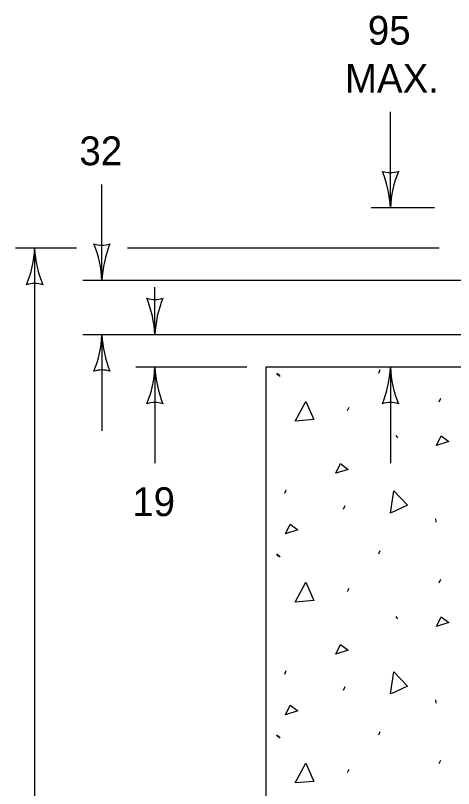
# Model space of a CAD drawing. Extents: x 49940 to 50043, y 49986 to 50011.
# Drawn here: x 50026.782 to 50027.696, y 49992.517 to 49994.127 of the extents above; entities that cross this region are included whole.
import ezdxf

# ---------------------------------------------------------------- set-up
doc = ezdxf.new("R2010")
doc.units = 0
for name, color, linetype in [('Level 1', 7, 'Continuous'), ('Level 2', 7, 'Continuous'), ('Level 3', 7, 'Continuous')]:
    doc.layers.add(name, color=color, linetype=linetype)

msp = doc.modelspace()

# ---------------------------------------------------------------- linework, layer by layer
at = {"layer": 'Level 1'}
for p, q in [((50027.8502, 49993.3945), (50027.3049, 49993.3945)), ((50027.3049, 49993.3945), (50027.3049, 49990.6682)), ((50027.3272, 49993.3824), (50027.3305, 49993.3775)), ((50027.5402, 49993.3824), (50027.5435, 49993.3897)), ((50027.3305, 49993.3805), (50027.3338, 49993.3755)), ((50027.6661, 49993.3225), (50027.6694, 49993.3298)), ((50027.4749, 49993.304), (50027.4782, 49993.3113)), ((50027.5759, 49993.2522), (50027.5791, 49993.2474)), ((50027.3442, 49993.132), (50027.3474, 49993.1393)), ((50027.4669, 49993.099), (50027.47, 49993.1063)), ((50027.6587, 49993.0787), (50027.6594, 49993.0714)), ((50027.5402, 49993.0054), (50027.5435, 49993.0126)), ((50027.3272, 49993.0054), (50027.3305, 49993.0004)), ((50027.3305, 49993.0036), (50027.3338, 49992.9987)), ((50027.6661, 49992.9455), (50027.6694, 49992.9528)), ((50027.4749, 49992.927), (50027.4782, 49992.9343)), ((50027.5759, 49992.8753), (50027.5791, 49992.8705)), ((50027.3442, 49992.755), (50027.3474, 49992.7623)), ((50027.4669, 49992.7219), (50027.47, 49992.7293)), ((50027.6587, 49992.7017), (50027.6594, 49992.6944)), ((50027.3272, 49992.6283), (50027.3305, 49992.6236)), ((50027.3305, 49992.6265), (50027.3338, 49992.6218)), ((50027.5402, 49992.6283), (50027.5435, 49992.6357)), ((50027.6661, 49992.5686), (50027.6694, 49992.5758)), ((50027.4749, 49992.55), (50027.4782, 49992.5573))]:
    msp.add_line(p, q, dxfattribs=at)
for points in [[(50027.3661, 49993.2821), (50027.3878, 49993.3233), (50027.4048, 49993.2853), (50027.3668, 49993.2821)], [(50027.6605, 49993.2313), (50027.6702, 49993.2515), (50027.6863, 49993.2394), (50027.6605, 49993.2313)], [(50027.4508, 49993.1736), (50027.4606, 49993.1936), (50027.4767, 49993.1816), (50027.4508, 49993.1736)], [(50027.565, 49993.0907), (50027.5715, 49993.1368), (50027.6003, 49993.1069), (50027.5658, 49993.0909)], [(50027.3458, 49993.0473), (50027.3555, 49993.0674), (50027.3716, 49993.0554), (50027.3458, 49993.0473)], [(50027.3661, 49992.9052), (50027.3878, 49992.9463), (50027.4048, 49992.9084), (50027.3668, 49992.9052)], [(50027.6605, 49992.8543), (50027.6702, 49992.8744), (50027.6863, 49992.8624), (50027.6605, 49992.8543)], [(50027.4508, 49992.7966), (50027.4606, 49992.8168), (50027.4767, 49992.8047), (50027.4508, 49992.7966)], [(50027.565, 49992.7136), (50027.5715, 49992.7597), (50027.6003, 49992.7299), (50027.5658, 49992.714)], [(50027.3458, 49992.6703), (50027.3555, 49992.6905), (50027.3716, 49992.6784), (50027.3458, 49992.6703)], [(50027.3661, 49992.5283), (50027.3878, 49992.5694), (50027.4048, 49992.5314), (50027.3668, 49992.5283)]]:
    msp.add_lwpolyline(points, dxfattribs=at)
at = {"layer": 'Level 3'}
for p, q in [((50027.5645, 49993.7266), (50027.5645, 49993.9266)), ((50026.9629, 49993.5754), (50026.9629, 49993.7754)), ((50027.6567, 49993.7266), (50027.5245, 49993.7266)), ((50026.9095, 49993.6425), (50026.7825, 49993.6425)), ((50026.8225, 49993.6425), (50026.8225, 49990.8092)), ((50027.6662, 49993.6425), (50027.0162, 49993.6425)), ((50027.9924, 49993.5749), (50026.9229, 49993.5749)), ((50027.0733, 49993.4622), (50027.0733, 49993.5615)), ((50027.7443, 49993.4622), (50026.9229, 49993.4622)), ((50026.9629, 49993.4622), (50026.9629, 49993.2622)), ((50027.2649, 49993.3945), (50027.0333, 49993.3945)), ((50027.0733, 49993.3945), (50027.0733, 49993.1945)), ((50027.5645, 49993.3945), (50027.5645, 49993.1945))]:
    msp.add_line(p, q, dxfattribs=at)
for centre, radius, start, end in [((50027.5645, 49993.8548), 0.0548, 252.1388, 287.8612), ((50027.3318, 49993.7151), 0.233, 2.8273, 22.0772), ((50027.7866, 49993.7174), 0.2223, 157.456, 177.6395), ((50026.6004, 49993.6517), 0.2223, 337.456, 357.6395), ((50027.0552, 49993.654), 0.233, 182.8273, 202.0772), ((50026.9629, 49993.7036), 0.0548, 252.1388, 287.8612), ((50026.7302, 49993.5639), 0.233, 2.8273, 22.0772), ((50027.185, 49993.5662), 0.2223, 157.456, 177.6395), ((50026.8225, 49993.5143), 0.0548, 72.1388, 107.8612), ((50027.0733, 49993.5904), 0.0548, 252.1388, 287.8612), ((50026.8406, 49993.4507), 0.233, 2.8273, 22.0772), ((50027.2954, 49993.453), 0.2223, 157.456, 177.6395), ((50026.7408, 49993.4714), 0.2223, 337.456, 357.6395), ((50027.1956, 49993.4737), 0.233, 182.8273, 202.0772), ((50026.9629, 49993.334), 0.0548, 72.1388, 107.8612), ((50026.8512, 49993.4037), 0.2223, 337.456, 357.6395), ((50027.306, 49993.406), 0.233, 182.8273, 202.0772), ((50027.3424, 49993.4037), 0.2223, 337.456, 357.6395), ((50027.7972, 49993.406), 0.233, 182.8273, 202.0772), ((50027.0733, 49993.2663), 0.0548, 72.1388, 107.8612), ((50027.5645, 49993.2663), 0.0548, 72.1388, 107.8612)]:
    msp.add_arc(centre, radius, start, end, dxfattribs=at)

# ---------------------------------------------------------------- texts
at = {"layer": 'Level 2'}
for s, p in [('95', (50027.5175, 49994.0666)), ('MAX.', (50027.4697, 49993.9666)), ('32', (50026.9159, 49993.8154)), ('19', (50027.0261, 49993.0843))]:
    msp.add_text(s, height=0.06, dxfattribs=at).set_placement(p)

doc.saveas('drawing.dxf')
